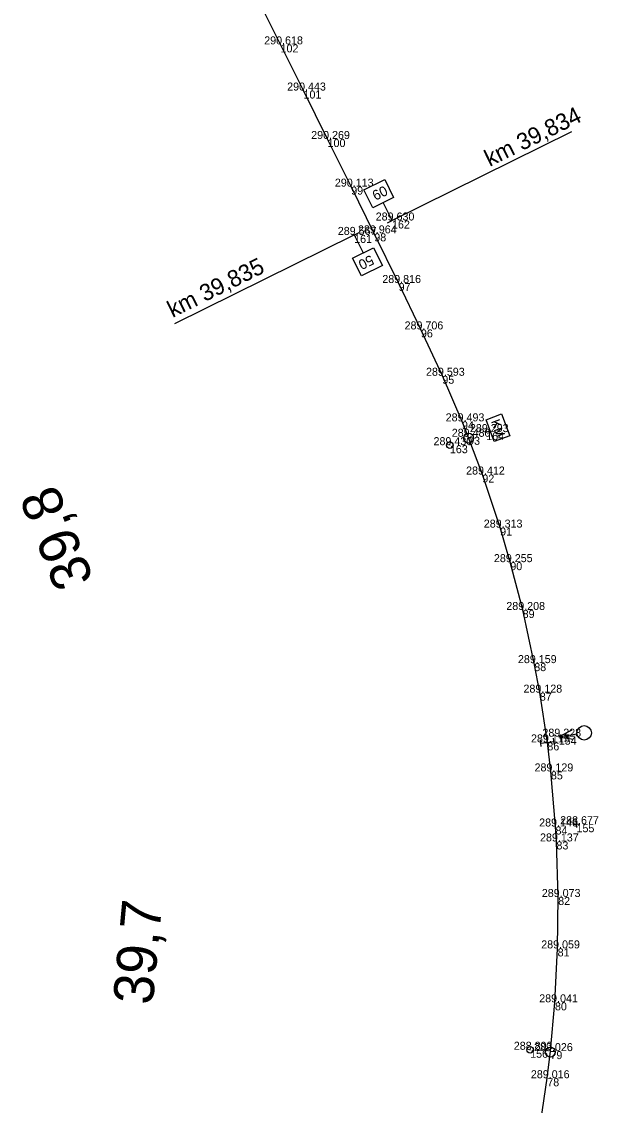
# Model space of a CAD drawing. Extents: x -684938 to -684389, y -1007777 to -1006471.
# Drawn here: x -684486.8 to -684400.4, y -1007619.2 to -1007456.7 of the extents above; entities that cross this region are included whole.
import ezdxf

# ---------------------------------------------------------------- set-up
doc = ezdxf.new("R2010")
doc.units = 0
for name, color, linetype in [('Vrstva 1', 7, 'Continuous'), ('Vrstva 3', 7, 'Continuous'), ('Vrstva 5', 7, 'Continuous'), ('Vrstva 60', 7, 'Continuous'), ('Vrstva 61', 7, 'Continuous'), ('Vrstva 7', 7, 'Continuous')]:
    doc.layers.add(name, color=color, linetype=linetype)

msp = doc.modelspace()

# ---------------------------------------------------------------- linework, layer by layer
at = {"layer": 'Vrstva 1'}
msp.add_lwpolyline([(-684409.29, -1007623.27), (-684408.06, -1007615.14), (-684407.59, -1007611.07), (-684406.91, -1007603.76), (-684406.51, -1007595.67), (-684406.43, -1007587.96), (-684406.69, -1007579.63), (-684406.83, -1007577.39), (-684407.52, -1007569.13), (-684408.05, -1007564.78), (-684409.18, -1007557.32), (-684410.01, -1007552.89), (-684411.75, -1007544.92), (-684413.6, -1007537.75), (-684415.13, -1007532.57), (-684417.79, -1007524.61), (-684419.93, -1007518.95), (-684420.84, -1007516.64), (-684423.79, -1007509.8), (-684427, -1007502.85), (-684430.34, -1007495.89), (-684433.99, -1007488.45), (-684437.45, -1007481.44), (-684440.99, -1007474.3), (-684444.6, -1007467.03), (-684448.04, -1007460.11), (-684451.43, -1007453.3)], dxfattribs=at)
at = {"layer": 'Vrstva 3'}
for p, q in [((-684406.34, -1007563.92), (-684403.61, -1007563.51)), ((-684408.98, -1007565.4), (-684409.1, -1007564.4)), ((-684409.04, -1007564.9), (-684407.05, -1007564.66)), ((-684406.99, -1007565.16), (-684407.11, -1007564.16))]:
    msp.add_line(p, q, dxfattribs=at)
msp.add_lwpolyline([(-684404.39, -1007562.93), (-684406.34, -1007563.92), (-684404.18, -1007564.29)], dxfattribs=at)
msp.add_circle((-684402.53, -1007563.35), 1.08, dxfattribs=at)
at = {"layer": 'Vrstva 5'}
for p, q in [((-684404.43, -1007473.24), (-684431.33, -1007486.52)), ((-684431.33, -1007486.52), (-684432.66, -1007483.83)), ((-684432, -1007486.86), (-684430.66, -1007486.19)), ((-684463.9, -1007501.97), (-684437.01, -1007488.68)), ((-684436.33, -1007488.35), (-684437.68, -1007489.02)), ((-684437.01, -1007488.68), (-684435.68, -1007491.37))]:
    msp.add_line(p, q, dxfattribs=at)
for points in [[(-684431.09, -1007483.06), (-684434.23, -1007484.61), (-684435.55, -1007481.92), (-684432.42, -1007480.37)], [(-684437.25, -1007492.15), (-684434.11, -1007490.6), (-684432.78, -1007493.29), (-684435.92, -1007494.84)]]:
    msp.add_lwpolyline(points, close=True, dxfattribs=at)
at = {"layer": 'Vrstva 60'}
for p, q in [((-684448.04, -1007460.11), (-684448.04, -1007460.11)), ((-684444.6, -1007467.03), (-684444.6, -1007467.03)), ((-684440.99, -1007474.3), (-684440.99, -1007474.3)), ((-684437.45, -1007481.44), (-684437.45, -1007481.44)), ((-684431.33, -1007486.52), (-684431.33, -1007486.52)), ((-684437.01, -1007488.68), (-684437.01, -1007488.68)), ((-684433.99, -1007488.45), (-684433.99, -1007488.45)), ((-684430.34, -1007495.89), (-684430.34, -1007495.89)), ((-684427, -1007502.85), (-684427, -1007502.85)), ((-684423.79, -1007509.8), (-684423.79, -1007509.8)), ((-684420.84, -1007516.64), (-684420.84, -1007516.64)), ((-684417.21, -1007518.25), (-684417.21, -1007518.25)), ((-684419.93, -1007518.95), (-684419.93, -1007518.95)), ((-684422.66, -1007520.21), (-684422.66, -1007520.21)), ((-684417.79, -1007524.61), (-684417.79, -1007524.61)), ((-684415.13, -1007532.57), (-684415.13, -1007532.57)), ((-684413.6, -1007537.75), (-684413.6, -1007537.75)), ((-684411.75, -1007544.92), (-684411.75, -1007544.92)), ((-684410.01, -1007552.89), (-684410.01, -1007552.89)), ((-684409.18, -1007557.32), (-684409.18, -1007557.32)), ((-684406.34, -1007563.92), (-684406.34, -1007563.92)), ((-684408.05, -1007564.78), (-684408.05, -1007564.78)), ((-684407.52, -1007569.13), (-684407.52, -1007569.13)), ((-684406.83, -1007577.39), (-684406.83, -1007577.39)), ((-684403.68, -1007577.05), (-684403.68, -1007577.05)), ((-684406.69, -1007579.63), (-684406.69, -1007579.63)), ((-684406.43, -1007587.96), (-684406.43, -1007587.96)), ((-684406.51, -1007595.67), (-684406.51, -1007595.67)), ((-684406.91, -1007603.76), (-684406.91, -1007603.76)), ((-684410.63, -1007610.87), (-684410.63, -1007610.87)), ((-684407.59, -1007611.07), (-684407.59, -1007611.07)), ((-684408.06, -1007615.14), (-684408.06, -1007615.14))]:
    msp.add_line(p, q, dxfattribs=at)
at = {"layer": 'Vrstva 7'}
for p, q in [((-684415.24, -1007516.42), (-684416.4, -1007516.86)), ((-684414.94, -1007517.2), (-684416.02, -1007516.71)), ((-684417.21, -1007518.25), (-684416.62, -1007518.03)), ((-684415.63, -1007516.89), (-684416.11, -1007517.64)), ((-684422.64, -1007520.25), (-684422.67, -1007520.16)), ((-684403.64, -1007577.55), (-684403.72, -1007576.55)), ((-684404.18, -1007577.09), (-684403.18, -1007577.01)), ((-684410.64, -1007610.92), (-684410.63, -1007610.82))]:
    msp.add_line(p, q, dxfattribs=at)
msp.add_lwpolyline([(-684417.24, -1007516.4), (-684414.92, -1007515.52), (-684413.68, -1007518.79), (-684416.01, -1007519.66)], close=True, dxfattribs=at)
msp.add_lwpolyline([(-684415.96, -1007518.03), (-684414.8, -1007517.59), (-684415.79, -1007518.48), (-684414.46, -1007518.48), (-684415.63, -1007518.92)], dxfattribs=at)
for centre, radius in [((-684419.85, -1007519.15), 0.75), ((-684422.66, -1007520.21), 0.5), ((-684410.63, -1007610.87), 0.5), ((-684407.61, -1007611.22), 0.75)]:
    msp.add_circle(centre, radius, dxfattribs=at)

# ---------------------------------------------------------------- texts
at = {"layer": 'Vrstva 5'}
for s, height, rotation, p in [('km 39,834', 2.5, 26.2863, (-684416.7, -1007478.49)), ('60', 1.5, 26.2863, (-684433.81, -1007483.57)), ('km 39,835', 2.5, 26.2863, (-684464.23, -1007501.14)), ('50', 1.5, 206.2863, (-684434.53, -1007491.64))]:
    msp.add_text(s, height=height, rotation=rotation, dxfattribs=at).set_placement(p)
at = {"layer": 'Vrstva 60'}
for s, p in [('102', (-684448.04, -1007461.31)), ('101', (-684444.6, -1007468.23)), ('100', (-684440.99, -1007475.5)), ('99', (-684437.45, -1007482.64)), ('162', (-684431.33, -1007487.72)), ('161', (-684437.01, -1007489.88)), ('98', (-684433.99, -1007489.65)), ('97', (-684430.34, -1007497.09)), ('96', (-684427, -1007504.05)), ('95', (-684423.79, -1007511)), ('94', (-684420.84, -1007517.84)), ('164', (-684417.21, -1007519.45)), ('93', (-684419.93, -1007520.15)), ('163', (-684422.66, -1007521.41)), ('92', (-684417.79, -1007525.81)), ('91', (-684415.13, -1007533.77)), ('90', (-684413.6, -1007538.95)), ('89', (-684411.75, -1007546.12)), ('88', (-684410.01, -1007554.09)), ('87', (-684409.18, -1007558.52)), ('154', (-684406.34, -1007565.12)), ('86', (-684408.05, -1007565.98)), ('85', (-684407.52, -1007570.33)), ('84', (-684406.83, -1007578.59)), ('155', (-684403.68, -1007578.25)), ('83', (-684406.69, -1007580.83)), ('82', (-684406.43, -1007589.16)), ('81', (-684406.51, -1007596.87)), ('80', (-684406.91, -1007604.96)), ('156', (-684410.63, -1007612.07)), ('79', (-684407.59, -1007612.27)), ('78', (-684408.06, -1007616.34))]:
    msp.add_text(s, height=1.2, dxfattribs=at).set_placement(p)
at = {"layer": 'Vrstva 61'}
for s, p in [('290.618', (-684450.49, -1007460.11)), ('290.443', (-684447.05, -1007467.03)), ('290.269', (-684443.45, -1007474.3)), ('290.113', (-684439.9, -1007481.44)), ('289.630', (-684433.78, -1007486.52)), ('289.567', (-684439.46, -1007488.68)), ('289.964', (-684436.44, -1007488.45)), ('289.816', (-684432.79, -1007495.89)), ('289.706', (-684429.45, -1007502.85)), ('289.593', (-684426.24, -1007509.8)), ('289.493', (-684423.29, -1007516.64)), ('289.480', (-684422.38, -1007518.95)), ('289.293', (-684419.66, -1007518.25)), ('289.430', (-684425.11, -1007520.21)), ('289.412', (-684420.23, -1007524.61)), ('289.313', (-684417.58, -1007532.57)), ('289.255', (-684416.06, -1007537.75)), ('289.208', (-684414.2, -1007544.92)), ('289.159', (-684412.46, -1007552.89)), ('289.128', (-684411.63, -1007557.32)), ('289.115', (-684410.5, -1007564.78)), ('289.228', (-684408.79, -1007563.92)), ('289.129', (-684409.97, -1007569.13)), ('289.146', (-684409.28, -1007577.39)), ('288.677', (-684406.13, -1007577.05)), ('289.137', (-684409.15, -1007579.63)), ('289.073', (-684408.88, -1007587.96)), ('289.059', (-684408.97, -1007595.67)), ('289.041', (-684409.27, -1007603.76)), ('288.893', (-684413.08, -1007610.87)), ('289.026', (-684410.04, -1007611.07)), ('289.016', (-684410.52, -1007615.14))]:
    msp.add_text(s, height=1.2, dxfattribs=at).set_placement(p)
at = {"layer": 'Vrstva 7'}
for s, rotation, p in [('39,8', 111.5093, (-684475.98, -1007540.37)), ('39,7', 84.7214, (-684467.2, -1007604.25))]:
    msp.add_text(s, height=6, rotation=rotation, dxfattribs=at).set_placement(p)

doc.saveas('drawing.dxf')
